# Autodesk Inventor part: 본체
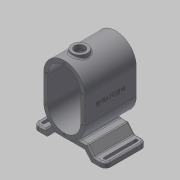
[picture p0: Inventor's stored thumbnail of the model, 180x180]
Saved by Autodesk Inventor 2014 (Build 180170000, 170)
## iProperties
Created: 2016-12
Part Number: 본체
Material: 일반
Document SubType Name: Modeling
Designer: mduedu
Density: 1 g/cm^3
Appearance: 기본값
Author: mduedu
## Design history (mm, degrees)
sketch "스케치1"
  geometry: L1 (40, -25)-(40, 25); L2 (-40, 25)-(-40, -25); L3 (-40, -25)-(40, 25); L4 (40, -25)-(-40, 25); L5 (0, 25)-(0, -25); A1 r 40 centre (0, 25) between (40, 25) and (-40, 25); A2 r 40 centre (0, -25) between (-40, -25) and (40, -25); 1 further point
  constraints: 10 end point, 4 point on circle, 3 tangent, 2 centre point, 2 midpoint, 2 parallel, 1 vertical
  dimensions: "d0" = 130 dimension on A2 A1; "d2" = 80 distance between parallel lines of L1 L2
extrude "돌출1" new body sketch "스케치1" stored distance "d3" = 100; taper "d4" = 0 deg
feature "쉘1" dims "d5" = 8
sketch "스케치15"
  geometry: L1 (-35, -64.5)-(35, -64.5); L2 (-35, -64.5)-(-47.586, -79.5); L3 (-47.586, -79.5)-(-70, -79.5); L4 (0, -64.5)-(0, 0); L5 (35, -64.5)-(47.586, -79.5); L6 (47.586, -79.5)-(70, -79.5); L7 (70, -89.5)-(42.923, -89.5); L8 (42.923, -89.5)-(30.337, -74.5); L9 (30.337, -74.5)-(-30.337, -74.5); L10 (-30.337, -74.5)-(-42.923, -89.5); L11 (-42.923, -89.5)-(-70, -89.5); L12 (-70, -79.5)-(-70, -89.5); L13 (70, -79.5)-(70, -89.5); A1 r 40 centre (0, -25) between (-40, -25) and (40, -25) reference; 1 further point
  constraints: 26 end point, 2 parallel, 2 perpendicular, 2 symmetric about line, 1 coincident, 1 horizontal, 1 midpoint, 1 vertical, 4 other
  dimensions: "d83" = 10 distance between parallel lines of L9 L1; "d85" = 140 distance between parallel lines of L13 L12; "d86" = 70 distance of L1.start L1.end; "d87" = 25 distance between parallel lines of L11 L1; "d88" = 130 deg angle of L1 L2; "d106" = 0.5 distance edge to line of A1 L1
extrude "돌출6" new body sketch "스케치15" stored distance "d89" = 80; taper "d90" = 0 deg
fillet "모깎기13" dims "d101" = 3
fillet "모깎기15" dims "d103" = 3
fillet "모깎기16" dims "d104" = 10
fillet "모깎기17" dims "d105" = 3
feature "결합2"
  node "솔리드2"
fillet "모깎기18" dims "d107" = 3
sketch "스케치16"
  geometry: L1 (8.015, 67)-(8.015, 7); L2 (14.015, 67)-(14.015, 7); A1 r 10 centre (11.015, 67) between (21.015, 67) and (11.015, 77) reference; A2 r 10 centre (11.015, 7) between (11.015, -3) and (21.015, 7) reference; A3 r 3 centre (11.015, 67) between (8.015, 67) and (14.015, 67); A4 r 3 centre (11.015, 7) between (8.015, 7) and (14.015, 7); 1 further point
  constraints: 4 end point, 4 point on circle, 4 tangent, 2 centre point, 2 coincident
  dimensions: "d108" = 6 diameter of A3; "d109" = 6 diameter of A4
extrude "돌출7" cut sketch "스케치16" stored distance "d110" = 80; taper "d111" = 0 deg
node "작업 평면1"
sketch "스케치9"
  geometry: 1 further point
sketch "스케치7"
  geometry: L1 (40, 50)-(-40, 50) reference; C1 r 15 at (0, 20); 1 further point
  constraints: 1 centre point, 1 vertical alignment
  dimensions: "d40" = 30 diameter of C1; "d41" = 30 distance from line of C1.centre L1
extrude "돌출4" join sketch "스케치7" stored distance "d42" = 80; taper "d43" = 0 deg
hole "구멍2" diameter "d46" = 20; stored, may be unused: countersink angle "d50" = 90 deg, drill point angle "d52" = 118 deg; dims "d44" = 10, "d45" = 10, "d47" = 6, "d48" = 4, "d49" = 2, "d51" = 8
fillet "모깎기4" dims "d53" = 3
node "작업 평면2"
sketch "스케치8"
  geometry: C1 r 15 at (0, 0) reference; C2 r 15 at (0, 0); 1 further point
  constraints: 1 centre point, 1 coincident
  dimensions: "d55" = 30 diameter of C2
extrude "돌출5" cut sketch "스케치8" stored distance "d56" = 80; taper "d57" = 0 deg
chamfer "모따기1" distance "d58" = 1; stored, may be unused: second distance "d59" = 2, angle "d60" = 45 deg
sketch "스케치10"
  geometry: 2 further points
  constraints: 1 coincident, 1 other
feature "엠보싱1" sketch "스케치10" dims "d0" = 130, "d2" = 80, "d61" = 0.5, "d62" = 0
sketch "스케치11"
  geometry: 1 further point
  constraints: 1 other
hole "구멍3" sketch "스케치11" at (0, 60) diameter "d63" = 3.242; stored, may be unused: countersink angle "d67" = 90 deg, drill point angle "d69" = 120 deg; dims "d64" = 8.6, "d65" = 4, "d66" = 2, "d68" = 10.6
sketch "스케치12"
  geometry: 1 further point
  constraints: 1 other
hole "구멍5" sketch "스케치12" at (0, 60) diameter "d70" = 3.242; stored, may be unused: countersink angle "d74" = 90 deg, drill point angle "d76" = 120 deg; dims "d71" = 8.6, "d72" = 4, "d73" = 2, "d75" = 10.6
node "솔리드1"
mirror "대칭2"
pattern_linear "직사각형 패턴1"
pattern_linear "직사각형 패턴2"
sketch "스케치13"
  geometry: L1 (-40, 25)-(-40, -25) reference; L2 (40, -25)-(40, 25) reference; L3 (35, 25)-(35, -25); L4 (-35, -25)-(-35, 25); A1 r 40 centre (0, 25) between (40, 25) and (-40, 25) reference; A2 r 40 centre (0, -25) between (-40, -25) and (40, -25) reference; A3 r 35 centre (0, 25) between (35, 25) and (-35, 25); A4 r 35 centre (0, -25) between (-35, -25) and (35, -25); 2 further points
  constraints: 5 point on circle, 4 end point, 2 centre point, 3 other
  dimensions: "d77" = 5 distance between parallel lines of L3 L2
sketch "스케치14"
  geometry: L1 (-40, 25)-(-40, -25) reference; L2 (40, -25)-(40, 25) reference; L3 (35, 25)-(35, -25); L4 (-35, -25)-(-35, 25); A1 r 40 centre (0, 25) between (40, 25) and (-40, 25) reference; A2 r 40 centre (0, -25) between (-40, -25) and (40, -25) reference; A3 r 35 centre (0, 25) between (35, 25) and (-35, 25); A4 r 35 centre (0, -25) between (-35, -25) and (35, -25); 2 further points
  constraints: 5 point on circle, 4 end point, 2 centre point, 3 other
  dimensions: "d80" = 5 distance between parallel lines of L2 L3
other parameters: "d54" = -8
